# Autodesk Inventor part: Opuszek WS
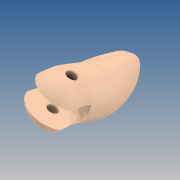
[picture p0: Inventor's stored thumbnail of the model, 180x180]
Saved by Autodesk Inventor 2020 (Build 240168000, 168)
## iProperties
Created: 2019-10
Part Number: Opuszek WS
Material: GFRP
Document SubType Name: Modeling
Designer: yello
Density: 1.75 g/cm^3
Appearance: Default
Author: yello
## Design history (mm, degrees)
feature "Opuszek WS"
sketch "Sketch1"
  geometry: C1 r 2 at (0, 0); 1 further point
  constraints: 1 centre point
  dimensions: "d0" = 4 diameter of C1
extrude "Extrusion1" cut sketch "Sketch1" stored distance "d1" = 100; taper "d2" = 0 deg
body "Solid1"
